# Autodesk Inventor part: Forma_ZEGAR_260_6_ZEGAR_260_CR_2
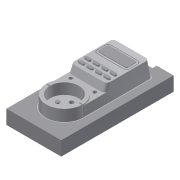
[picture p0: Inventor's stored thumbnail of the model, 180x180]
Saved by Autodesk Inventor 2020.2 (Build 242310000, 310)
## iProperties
Created: 2015-01
Part Number: Forma_ZEGAR_260_6_ZEGAR_260_CR_2
Material: Ogólny
Document SubType Name: Modeling
Designer: F.Stasiak
Density: 1 g/cm^3
Appearance: Domyślna
Catalog Web Link: www.expertbooks.pl
Manager: www.cadconsulting.pl
Company: Fabian Stasiak CAD Consulting
Author: F.Stasiak
Subject: Zbiór ćwiczeń. Autodesk Inventor 2020. Kurs Professional
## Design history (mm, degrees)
node "Forma_ZEGAR_260_4_ZEGAR_260_CR_Base"
feature "Bryła1::Forma_ZEGAR_260_4_ZEGAR_260_CR_Base"
tag "Bryła wyprowadzona1"
node "Bryła1"
feature "Forma_ZEGAR_260_4_ZEGAR_260_CR_Base_Bodies"
